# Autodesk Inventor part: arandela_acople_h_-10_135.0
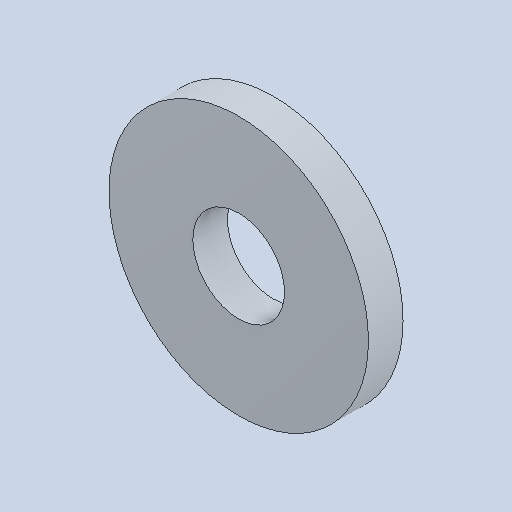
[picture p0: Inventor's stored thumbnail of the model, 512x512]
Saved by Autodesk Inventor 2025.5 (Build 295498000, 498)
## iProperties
Created: 2026-10
Part Number: arandela_acople_h_-10_135.0
Material: Genérico
Document SubType Name: Modeling
Designer: Luis M
Density: 1 g/cm^3
Appearance: Valor por defecto
Author: Luis M
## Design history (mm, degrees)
feature "Base1"
node "Sólido1"
